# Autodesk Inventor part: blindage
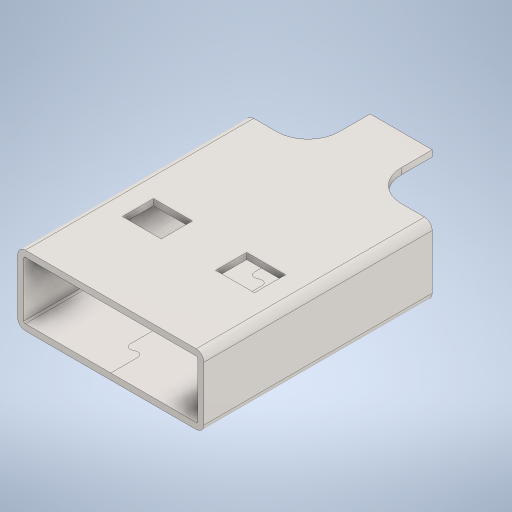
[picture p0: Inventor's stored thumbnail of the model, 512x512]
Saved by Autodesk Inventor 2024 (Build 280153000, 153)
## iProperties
Created: 2014-05
Part Number: blindage
Material: SolidWorks DIN Materials|1.4000 (X6Cr13)
Document SubType Name: Modeling
Designer: TVANDROUX
Density: 7.8 g/cm^3
Appearance: 198,193,188
Sending System: SolidWorks 2010
Last Author: Jonathan
Last Saved: 2014-05-14
Author: TVANDROUX
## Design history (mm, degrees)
node "Congé1"
sketch "Esquisse1"
  geometry: L1 (0, -4)-(5.5, -4) reference; L2 (5.5, -4)-(11, -4) reference; L3 (11, 0)-(0, 0) reference; L4 (7.5, -4)-(3.5, -4); L5 (3.5, -2)-(3.5, 0); L6 (3.5, 0)-(7.5, 0); L7 (7.5, 0)-(7.5, -2); L8 (-0.5, -18.7)-(-0.5, 0) reference; L9 (12.633, -4)-(9.5, -4); L10 (11.5, -18.7)-(11.5, 0) reference; L11 (-3.687, -4)-(1.5, -4); L12 (12.633, -4)-(12.633, 3.79); L13 (12.633, 3.79)-(-3.687, 3.79); L14 (-3.687, 3.79)-(-3.687, -4); A1 r 2 centre (1.5, -2) between (1.5, -4) and (3.5, -2); A2 r 2 centre (9.5, -2) between (7.5, -2) and (9.5, -4); 6 further points
  constraints: 18 end point, 7 point on line, 4 perpendicular, 4 point on circle, 4 tangent, 2 centre point, 2 parallel, 1 collinear, 1 equal radius, 1 horizontal, 1 vertical
  dimensions: "d0" = 4 distance between parallel lines of L5 L7; "d1" = 4 distance between parallel lines of L8 L5; "d2" = 2 radius of A1 (derived)
extrude "Extrusion1" cut sketch "Esquisse1" distance "d3" = 10; taper "d4" = 0 deg
node "Solide1"
